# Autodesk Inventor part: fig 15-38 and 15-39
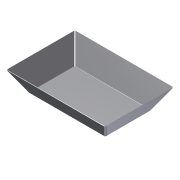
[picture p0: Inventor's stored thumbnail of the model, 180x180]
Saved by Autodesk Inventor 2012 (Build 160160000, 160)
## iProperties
Created: 2007-05
Part Number: fig 15-38 and 15-39
Document SubType Name: Sheet Metal
Designer: Administrator
Density: 1 g/cm^3
Sheet Metal Rule: Default
Material: Default
Author: Administrator
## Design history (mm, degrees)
node "Face1"
  sketch "Sketch1"
    geometry: L1 (-17.365, -15.579)-(32.635, -15.579); L2 (32.635, -15.579)-(32.635, 14.421); L3 (32.635, 14.421)-(-17.365, 14.421); L4 (-17.365, 14.421)-(-17.365, -15.579)
    constraints: 8 end point, 2 parallel, 1 horizontal, 1 perpendicular
    dimensions: "d0" = 30 distance of L3.end L1.start; "d1" = 50 distance of L1.start L1.end
node "Flange1"
body "Solid1"
face "Plate1" dims "Thickness" = 0.3
sketch "Sketch2"
  geometry: L1 (0, 15)-(-30, 15); L2 (-30, 15)-(-30, 0); 2 other entities
  constraints: 4 end point, 4 other
face "Plate2" dims "d3" = 0.3 (= BendReliefWidth), "d4" = 0.15 (= BendReliefDepth), "d5" = 0.6 (= MinimumRemnant), "d6" = 0.3 (= BendRadius), "d7" = 15, "d8" = 60 deg, "d9" = 0.3 (= BendRadius), "d10" = 1.2 (= CornerReliefSize), "d11" = 0.5, "d12" = 0.3 (= JacobiRadiusSize), "SeamGap" = 0.01, "Thickness" = 0.3
bend "Bend1" dims "d3" = 0.3 (= BendReliefWidth), "d4" = 0.15 (= BendReliefDepth), "d5" = 0.6 (= MinimumRemnant), "d6" = 0.3 (= BendRadius), "d7" = 15, "d8" = 60 deg, "d9" = 0.3 (= BendRadius), "SeamGap" = 0.01, "Thickness" = 0.3
feature "Corner1" dims "d7" = 15, "d8" = 60 deg, "d10" = 1.2 (= CornerReliefSize), "d11" = 0.5, "d12" = 0.3 (= JacobiRadiusSize)
other parameters: "BendRadius" = 0.3 (= Thickness), "BendReliefWidth" = 0.3 (= Thickness), "BendReliefDepth" = 0.15 (= 0.5 x Thickness), "CornerReliefSize" = 1.2 (= 4 x Thickness), "MinimumRemnant" = 0.6 (= 2 x Thickness), "TransitionRadius" = 0.3 (= BendRadius), "JacobiRadiusSize" = 0.3 (= Thickness), "d2" = 0.3 (= BendRadius), "GapSize" = 0.3 (= Thickness)
